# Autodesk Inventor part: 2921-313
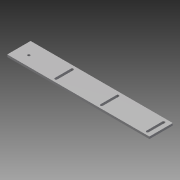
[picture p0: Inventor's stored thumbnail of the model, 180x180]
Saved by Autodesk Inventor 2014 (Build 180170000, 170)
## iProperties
Company: NHRTSA/VRTC
Created: 2012-02
Part Number: 2921-313
Project: CHILD SIDE IMPACT SLED
Material: Steel
Description: BENCH BEARING SUPPORT PLATE
Document SubType Name: Modeling
Designer: Mike Vanvoorhis
Mass: 4091.93 g
Surface Area: 1255.6 cm^2
Volume: 521.265 cm^3
Density: 7.85 g/cm^3
Appearance: Steel
Stock Number: PL 9.5 (3/8") x 102.0 (4") x 620.0 (24 7/16")
DESIGN DATE: 2012-11-05
Title: Bench Bearing Support Plate
Subject: Child Side Impact Sled
Author: Dave Walker
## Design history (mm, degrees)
sketch "Sketch1"
  geometry: L1 (-310, 0)-(310, 0); L2 (310, 0)-(310, -9.5); L3 (310, -9.5)-(-310, -9.5); L4 (-310, -9.5)-(-310, 0); L5 (0, 1.9)-(0, -11.4) reference; L6 (-434, 0)-(434, 0) reference
  constraints: 8 end point, 2 parallel, 1 collinear, 1 horizontal, 1 perpendicular, 1 other
  dimensions: "d0" = 620 distance of L1.start L1.end; "d1" = 9.5 distance of L3.end L1.start
extrude "Extrusion1" new body sketch "Sketch1" distance "d2" = 102; taper "d3" = 0 deg
sketch "Sketch4"
  geometry: L1 (0, 0)-(620, 0) reference; L2 (620, 0)-(620, 102) reference; 2 further points
  dimensions: "d36" = 44.45 distance from line of point (50, 44.45) L1; "d37" = 570 distance from line of point (50, 44.45) L2
hole "Hole3" sketch "Sketch4" at (50, 44.45) diameter "d29" = 11; stored, may be unused: countersink angle "d33" = 82 deg, drill point angle "d35" = 118 deg; dims "d30" = 6, "d31" = 3.023, "d32" = 2, "d34" = 8
sketch "Sketch5"
  geometry: L1 (0, 0)-(620, 0) reference; L2 (620, 0)-(620, 102) reference; 7 further points
  constraints: 4 horizontal alignment, 3 vertical alignment
  dimensions: "d38" = 15 distance from line of point (597, 15) L1; "d39" = 23 distance from line of point (597, 15) L2; "d40" = 223 distance from line of point (397, 15) L2; "d41" = 422 distance from line of point (198, 15) L2; "d49" = 70 distance of point (597, 85) point (597, 15)
hole "Hole4" sketch "Sketch5" at (597, 15), (397, 15), (198, 15), (597, 85), (397, 85), (198, 85) diameter "d42" = 11; stored, may be unused: countersink angle "d46" = 90 deg, drill point angle "d48" = 118 deg; dims "d43" = 6, "d44" = 4, "d45" = 2, "d47" = 8
sketch "Sketch6"
  geometry: L1 (192.5, 85)-(203.5, 85); L2 (203.5, 85)-(203.5, 15); L3 (203.5, 15)-(192.5, 15); L4 (192.5, 15)-(192.5, 85); L5 (402.5, 85)-(402.5, 15); L6 (391.5, 15)-(391.5, 85); L7 (391.5, 85)-(402.5, 85); L8 (402.5, 15)-(391.5, 15); L9 (602.5, 85)-(602.5, 15); L10 (591.5, 15)-(591.5, 85); L11 (591.5, 85)-(602.5, 85); L12 (602.5, 15)-(591.5, 15); C1 r 5.5 at (397, 85) reference; C2 r 5.5 at (198, 15) reference; C3 r 5.5 at (597, 15) reference; C4 r 5.5 at (397, 15) reference; C5 r 5.5 at (597, 85) reference; C6 r 5.5 at (198, 85) reference; 2 further points
  constraints: 24 end point, 6 midpoint, 6 parallel, 6 tangent, 3 horizontal, 3 perpendicular, 1 coincident
extrude "Extrusion2" cut sketch "Sketch6" stored distance "d50" = 10; taper "d51" = 0 deg
body "Solid1"
